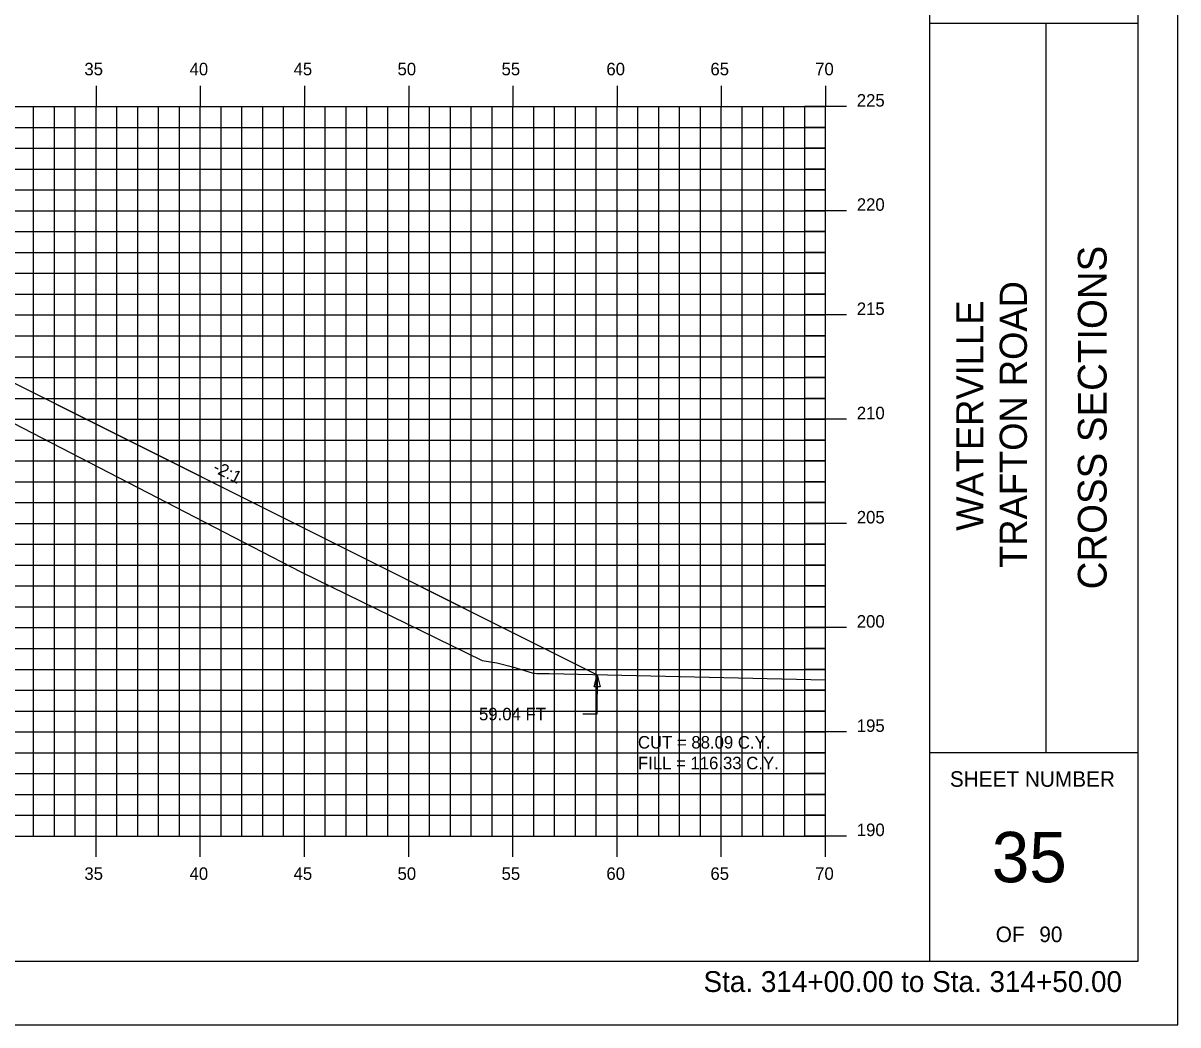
# Model space of a CAD drawing. Extents: x 1138320 to 1138490, y 608981 to 609091.
# Drawn here: x 1138434.2 to 1138489.6, y 608981.3 to 609029.3 of the extents above; entities that cross this region are included whole.
import ezdxf

# ---------------------------------------------------------------- set-up
doc = ezdxf.new("R2010")
doc.units = 0
for name, color, linetype in [('ANNOTATION', 7, 'Continuous'), ('BORDER', 7, 'Continuous'), ('D_Roadway_SlopeLines', 7, 'Continuous'), ('D_Text_Standard', 7, 'Continuous'), ('H_V ANNOTATION', 7, 'Continuous'), ('HIGHWAY_TITLE', 7, 'Continuous'), ('MAJOR', 7, 'Continuous'), ('MINOR', 7, 'Continuous'), ('PLOT BOUNDARY', 7, 'Continuous'), ('S_Roadway_Centerline', 7, 'Continuous')]:
    doc.layers.add(name, color=color, linetype=linetype)

msp = doc.modelspace()

# ---------------------------------------------------------------- linework, layer by layer
msp.add_lwpolyline([(1138342.969, 608997.503), (1138378.753, 609015.395), (1138380.753, 609016.395), (1138385.713, 609018.875), (1138385.714, 609018.875), (1138391.679, 609019.113), (1138402.679, 609019.333), (1138413.679, 609019.113), (1138420.167, 609018.854), (1138425.105, 609016.385), (1138427.105, 609015.385), (1138461.719, 608998.078)])
at = {"layer": 'BORDER'}
for p, q in [((1138477.679, 608984.335), (1138477.679, 609089.335)), ((1138477.679, 609029.338), (1138487.679, 609029.338)), ((1138483.27, 608994.338), (1138483.27, 609029.338)), ((1138477.679, 608994.338), (1138487.679, 608994.338))]:
    msp.add_line(p, q, dxfattribs=at)
msp.add_lwpolyline([(1138327.679, 608984.335), (1138487.679, 608984.335), (1138487.679, 609089.335), (1138327.679, 609089.335)], close=True, dxfattribs=at)
at = {"layer": 'D_Roadway_SlopeLines'}
for points in [[(1138423.716, 609017.079), (1138461.719, 608998.078)], [(1138427.105, 609015.385), (1138461.719, 608998.078)]]:
    msp.add_lwpolyline(points, dxfattribs=at)
at = {"layer": 'D_Text_Standard'}
msp.add_lwpolyline([(1138461.719, 608998.078), (1138461.71, 608996.189), (1138461.03, 608996.189)], dxfattribs=at)
msp.add_lwpolyline([(1138461.719, 608998.078), (1138461.862, 608997.495), (1138461.571, 608997.496)], close=True, dxfattribs=at)
at = {"layer": 'MAJOR'}
for p, q in [((1138437.679, 609026.337), (1138437.679, 609025.335)), ((1138442.679, 609026.337), (1138442.679, 609025.335)), ((1138447.679, 609026.337), (1138447.679, 609025.335)), ((1138452.679, 609026.337), (1138452.679, 609025.335)), ((1138457.679, 609026.337), (1138457.679, 609025.335)), ((1138462.679, 609026.337), (1138462.679, 609025.335)), ((1138467.679, 609026.337), (1138467.679, 609025.335)), ((1138472.679, 609026.337), (1138472.679, 609025.335)), ((1138332.679, 609025.335), (1138472.679, 609025.335)), ((1138332.679, 609025.335), (1138472.679, 609025.335)), ((1138437.679, 608990.335), (1138437.679, 609025.335)), ((1138442.679, 608990.335), (1138442.679, 609025.335)), ((1138447.679, 608990.335), (1138447.679, 609025.335)), ((1138452.679, 608990.335), (1138452.679, 609025.335)), ((1138457.679, 608990.335), (1138457.679, 609025.335)), ((1138462.679, 608990.335), (1138462.679, 609025.335)), ((1138467.679, 608990.335), (1138467.679, 609025.335)), ((1138473.681, 609025.335), (1138471.677, 609025.335)), ((1138472.679, 608990.335), (1138472.679, 609025.335)), ((1138472.679, 608990.335), (1138472.679, 609025.335)), ((1138332.679, 609020.335), (1138472.679, 609020.335)), ((1138473.681, 609020.335), (1138471.677, 609020.335)), ((1138332.679, 609015.335), (1138472.679, 609015.335)), ((1138473.681, 609015.335), (1138471.677, 609015.335)), ((1138332.679, 609010.335), (1138472.679, 609010.335)), ((1138473.681, 609010.335), (1138471.677, 609010.335)), ((1138332.679, 609005.335), (1138472.679, 609005.335)), ((1138473.681, 609005.335), (1138471.677, 609005.335)), ((1138332.679, 609000.335), (1138472.679, 609000.335)), ((1138473.681, 609000.335), (1138471.677, 609000.335)), ((1138332.679, 608995.335), (1138472.679, 608995.335)), ((1138473.681, 608995.335), (1138471.677, 608995.335)), ((1138332.679, 608990.335), (1138472.679, 608990.335)), ((1138332.679, 608990.335), (1138472.679, 608990.335)), ((1138437.679, 608989.333), (1138437.679, 608990.335)), ((1138442.679, 608989.333), (1138442.679, 608990.335)), ((1138447.679, 608989.333), (1138447.679, 608990.335)), ((1138452.679, 608989.333), (1138452.679, 608990.335)), ((1138457.679, 608989.333), (1138457.679, 608990.335)), ((1138462.679, 608989.333), (1138462.679, 608990.335)), ((1138467.679, 608989.333), (1138467.679, 608990.335)), ((1138473.681, 608990.335), (1138471.677, 608990.335)), ((1138472.679, 608989.333), (1138472.679, 608990.335))]:
    msp.add_line(p, q, dxfattribs=at)
at = {"layer": 'MINOR'}
for p, q in [((1138434.679, 608990.335), (1138434.679, 609025.335)), ((1138435.679, 608990.335), (1138435.679, 609025.335)), ((1138436.679, 608990.335), (1138436.679, 609025.335)), ((1138438.679, 608990.335), (1138438.679, 609025.335)), ((1138439.679, 608990.335), (1138439.679, 609025.335)), ((1138440.679, 608990.335), (1138440.679, 609025.335)), ((1138441.679, 608990.335), (1138441.679, 609025.335)), ((1138443.679, 608990.335), (1138443.679, 609025.335)), ((1138444.679, 608990.335), (1138444.679, 609025.335)), ((1138445.679, 608990.335), (1138445.679, 609025.335)), ((1138446.679, 608990.335), (1138446.679, 609025.335)), ((1138448.679, 608990.335), (1138448.679, 609025.335)), ((1138449.679, 608990.335), (1138449.679, 609025.335)), ((1138450.679, 608990.335), (1138450.679, 609025.335)), ((1138451.679, 608990.335), (1138451.679, 609025.335)), ((1138453.679, 608990.335), (1138453.679, 609025.335)), ((1138454.679, 608990.335), (1138454.679, 609025.335)), ((1138455.679, 608990.335), (1138455.679, 609025.335)), ((1138456.679, 608990.335), (1138456.679, 609025.335)), ((1138458.679, 608990.335), (1138458.679, 609025.335)), ((1138459.679, 608990.335), (1138459.679, 609025.335)), ((1138460.679, 608990.335), (1138460.679, 609025.335)), ((1138461.679, 608990.335), (1138461.679, 609025.335)), ((1138463.679, 608990.335), (1138463.679, 609025.335)), ((1138464.679, 608990.335), (1138464.679, 609025.335)), ((1138465.679, 608990.335), (1138465.679, 609025.335)), ((1138466.679, 608990.335), (1138466.679, 609025.335)), ((1138468.679, 608990.335), (1138468.679, 609025.335)), ((1138469.679, 608990.335), (1138469.679, 609025.335)), ((1138470.679, 608990.335), (1138470.679, 609025.335)), ((1138471.679, 608990.335), (1138471.679, 609025.335)), ((1138332.679, 609024.335), (1138472.679, 609024.335)), ((1138472.679, 609024.335), (1138471.677, 609024.335)), ((1138332.679, 609023.335), (1138472.679, 609023.335)), ((1138472.679, 609023.335), (1138471.677, 609023.335)), ((1138332.679, 609022.335), (1138472.679, 609022.335)), ((1138472.679, 609022.335), (1138471.677, 609022.335)), ((1138332.679, 609021.335), (1138472.679, 609021.335)), ((1138472.679, 609021.335), (1138471.677, 609021.335)), ((1138332.679, 609019.335), (1138472.679, 609019.335)), ((1138472.679, 609019.335), (1138471.677, 609019.335)), ((1138332.679, 609018.335), (1138472.679, 609018.335)), ((1138472.679, 609018.335), (1138471.677, 609018.335)), ((1138332.679, 609017.335), (1138472.679, 609017.335)), ((1138472.679, 609017.335), (1138471.677, 609017.335)), ((1138332.679, 609016.335), (1138472.679, 609016.335)), ((1138472.679, 609016.335), (1138471.677, 609016.335)), ((1138332.679, 609014.335), (1138472.679, 609014.335)), ((1138472.679, 609014.335), (1138471.677, 609014.335)), ((1138332.679, 609013.335), (1138472.679, 609013.335)), ((1138472.679, 609013.335), (1138471.677, 609013.335)), ((1138332.679, 609012.335), (1138472.679, 609012.335)), ((1138472.679, 609012.335), (1138471.677, 609012.335)), ((1138332.679, 609011.335), (1138472.679, 609011.335)), ((1138472.679, 609011.335), (1138471.677, 609011.335)), ((1138332.679, 609009.335), (1138472.679, 609009.335)), ((1138472.679, 609009.335), (1138471.677, 609009.335)), ((1138332.679, 609008.335), (1138472.679, 609008.335)), ((1138472.679, 609008.335), (1138471.677, 609008.335)), ((1138332.679, 609007.335), (1138472.679, 609007.335)), ((1138472.679, 609007.335), (1138471.677, 609007.335)), ((1138332.679, 609006.335), (1138472.679, 609006.335)), ((1138472.679, 609006.335), (1138471.677, 609006.335)), ((1138332.679, 609004.335), (1138472.679, 609004.335)), ((1138472.679, 609004.335), (1138471.677, 609004.335)), ((1138332.679, 609003.335), (1138472.679, 609003.335)), ((1138472.679, 609003.335), (1138471.677, 609003.335)), ((1138332.679, 609002.335), (1138472.679, 609002.335)), ((1138472.679, 609002.335), (1138471.677, 609002.335)), ((1138332.679, 609001.335), (1138472.679, 609001.335)), ((1138472.679, 609001.335), (1138471.677, 609001.335)), ((1138332.679, 608999.335), (1138472.679, 608999.335)), ((1138472.679, 608999.335), (1138471.677, 608999.335)), ((1138332.679, 608998.335), (1138472.679, 608998.335)), ((1138472.679, 608998.335), (1138471.677, 608998.335)), ((1138332.679, 608997.335), (1138472.679, 608997.335)), ((1138472.679, 608997.335), (1138471.677, 608997.335)), ((1138332.679, 608996.335), (1138472.679, 608996.335)), ((1138472.679, 608996.335), (1138471.677, 608996.335)), ((1138332.679, 608994.335), (1138472.679, 608994.335)), ((1138472.679, 608994.335), (1138471.677, 608994.335)), ((1138332.679, 608993.335), (1138472.679, 608993.335)), ((1138472.679, 608993.335), (1138471.677, 608993.335)), ((1138332.679, 608992.335), (1138472.679, 608992.335)), ((1138472.679, 608992.335), (1138471.677, 608992.335)), ((1138332.679, 608991.335), (1138472.679, 608991.335)), ((1138472.679, 608991.335), (1138471.677, 608991.335))]:
    msp.add_line(p, q, dxfattribs=at)
at = {"layer": 'PLOT BOUNDARY'}
msp.add_lwpolyline([(1138319.586, 608981.276), (1138489.586, 608981.276), (1138489.586, 609091.276), (1138319.586, 609091.276)], close=True, dxfattribs=at)
at = {"layer": 'S_Roadway_Centerline'}
msp.add_lwpolyline([(1138366.825, 609007.787), (1138384.799, 609017.593), (1138386.824, 609018.729), (1138390.25, 609019.291), (1138391.066, 609019.463), (1138391.53, 609019.519), (1138392.468, 609019.533), (1138402.971, 609019.723), (1138412.915, 609019.586), (1138413.616, 609019.576), (1138413.704, 609019.537), (1138416.182, 609019.216), (1138447.504, 609003.02), (1138456.197, 608998.757), (1138456.912, 608998.64), (1138457.654, 608998.458), (1138458.603, 608998.167), (1138458.832, 608998.129), (1138459.426, 608998.129), (1138472.679, 608997.833)], dxfattribs=at)

# ---------------------------------------------------------------- texts
at = {"layer": 'ANNOTATION'}
msp.add_text('-2:1', height=0.6, rotation=333.4349, dxfattribs=at).set_placement((1138443.235, 609007.838))
at = {"layer": 'BORDER'}
msp.add_text('CROSS SECTIONS', height=1.37787, rotation=90, dxfattribs=at).set_placement((1138486.164, 609002.172))
for s, height, p in [('SHEET NUMBER', 0.74527, (1138478.645, 608992.701)), ('35', 2.4194, (1138480.655, 608988.118)), ('OF', 0.7453, (1138480.846, 608985.248)), ('90', 0.7453, (1138482.936, 608985.248))]:
    msp.add_text(s, height=height, dxfattribs=at).set_placement(p)
at = {"layer": 'D_Text_Standard'}
for s, p in [('59.04 FT', (1138456.053, 608995.889)), ('CUT = 88.09 C.Y.', (1138463.679, 608994.535)), ('FILL = 116.33 C.Y.', (1138463.679, 608993.539))]:
    msp.add_text(s, height=0.6, dxfattribs=at).set_placement(p)
at = {"layer": 'H_V ANNOTATION'}
for s, height, p in [('35', 0.6, (1138437.12, 609026.835)), ('40', 0.6, (1138442.165, 609026.835)), ('45', 0.6, (1138447.157, 609026.835)), ('50', 0.6, (1138452.144, 609026.835)), ('55', 0.6, (1138457.136, 609026.835)), ('60', 0.6, (1138462.165, 609026.835)), ('65', 0.6, (1138467.157, 609026.835)), ('70', 0.6, (1138472.181, 609026.835)), ('225', 0.6, (1138474.179, 609025.335)), ('220', 0.6, (1138474.179, 609020.335)), ('215', 0.6, (1138474.179, 609015.335)), ('210', 0.6, (1138474.179, 609010.335)), ('205', 0.6, (1138474.179, 609005.335)), ('200', 0.6, (1138474.179, 609000.335)), ('195', 0.6, (1138474.179, 608995.335)), ('190', 0.6, (1138474.179, 608990.335)), ('35', 0.6, (1138437.12, 608988.235)), ('40', 0.6, (1138442.165, 608988.235)), ('45', 0.6, (1138447.157, 608988.235)), ('50', 0.6, (1138452.144, 608988.235)), ('55', 0.6, (1138457.136, 608988.235)), ('60', 0.6, (1138462.165, 608988.235)), ('65', 0.6, (1138467.157, 608988.235)), ('70', 0.6, (1138472.181, 608988.235)), ('Sta. 314+00.00 to Sta. 314+50.00', 1.0002, (1138466.825, 608982.855))]:
    msp.add_text(s, height=height, dxfattribs=at).set_placement(p)
at = {"layer": 'HIGHWAY_TITLE'}
for s, height, p in [('TRAFTON ROAD', 1.30428, (1138482.339, 609003.201)), ('WATERVILLE', 1.3043, (1138480.252, 609004.98))]:
    msp.add_text(s, height=height, rotation=90, dxfattribs=at).set_placement(p)

doc.saveas('drawing.dxf')
